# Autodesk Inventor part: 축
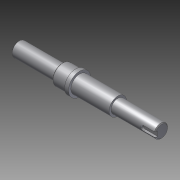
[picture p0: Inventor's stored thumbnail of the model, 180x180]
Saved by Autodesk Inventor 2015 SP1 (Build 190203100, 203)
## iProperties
Company: 한국ATC센터
Created: 2014-03
Part Number: 축
Document SubType Name: Modeling
Designer: KYOUNG IL JANG
Density: 1 g/cm^3
Material: 일반
Appearance: 기본값
Author: KYOUNG IL JANG
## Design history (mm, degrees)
sketch "스케치1"
  geometry: L1 (-102, 80)-(78, 80); L2 (-30.3, 106)-(-30.3, 54) reference; L3 (23, 99.7)-(23, 60.3) reference; L4 (-102, 80)-(-102, 89); L5 (-102, 89)-(-47, 89); L6 (-47, 89)-(-47, 92.5); L7 (-47, 92.5)-(-30, 92.5); L8 (-25, 94)-(-25, 91); L9 (-25, 91)-(23, 91); L10 (23, 91)-(23, 88.5); L11 (23, 88.5)-(78, 88.5); L12 (78, 88.5)-(78, 80); L13 (-30, 94)-(-25, 94); L14 (-31, 92.5)-(-44, 92.5) reference; L15 (-30, 105)-(-30, 55) reference; L16 (-30, 94)-(-30, 92.5); L17 (-68, 65.3)-(-68, 94.7) reference; L18 (-96, 89)-(-96, 85.5); L19 (-96, 85.5)-(-74, 85.5); L20 (-74, 85.5)-(-74, 89); L21 (60, 75)-(83, 75); L22 (83, 75)-(83, 71.5); L23 (83, 71.5)-(60, 71.5); L24 (60, 71.5)-(60, 75); 2 further points
  constraints: 40 end point, 12 perpendicular, 7 point on line, 3 horizontal, 3 parallel, 2 collinear, 1 midpoint, 1 other
  dimensions: "d0" = 18 diameter of L5 L1; "d1" = 17 distance of L6.end L7.end; "d2" = 5 distance of L13.start L8.start; "d3" = 28 diameter of L13 L1; "d4" = 22 diameter of L9 L1; "d5" = 17 diameter of L11 L1; "d8" = 34 distance between parallel lines of L17 L4; "d9" = 55 distance of L10.end L11.end; "d11" = 3.5 distance between parallel lines of L19 L5; "d12" = 22 distance between parallel lines of L20 L18; "d13" = 6 distance between parallel lines of L18 L4; "d14" = 17 diameter of L23 L1 (= d5); "d15" = 3.5 distance of L23.end L21.start (= d11); "d16" = 18 distance between parallel lines of L24 L12; "d17" = 23 distance of L22.end L23.end
  node "참조1"
  node "참조2"
  node "참조3"
  node "참조4"
revolve "회전1" stored, may be unused: angle "d10" = 90 deg
extrude "돌출1" cut sketch "스케치1" stored distance "d18" = 6; taper "d19" = 0 deg
fillet "모깎기1" dims "d20" = 3
chamfer "모따기1" distance "d21" = 1; stored, may be unused: second distance "d22" = 2, angle "d23" = 45 deg
node "솔리드1"
